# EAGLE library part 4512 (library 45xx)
8-channel DATA SELECTOR
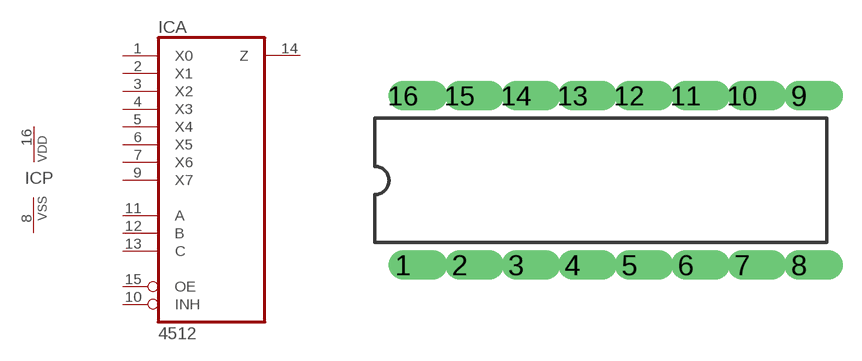
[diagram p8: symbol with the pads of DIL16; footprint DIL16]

Designator prefix IC; gates A=4512 P=PWRN

## 4512N  [DIL16]
1  A:X0  in
2  A:X1  in
3  A:X2  in
4  A:X3  in
5  A:X4  in
6  A:X5  in
7  A:X6  in
8  P:VSS  pwr
9  A:X7  in
10  A:INH  in
11  A:A  in
12  A:B  in
13  A:C  in
14  A:Z  hiz
15  A:OE  in
16  P:VDD  pwr

## Footprint DIL16 (pad centres in mm)
Dual In Line
drill 0.813 offset: 1 -8.89,-3.81; 2 -6.35,-3.81; 3 -3.81,-3.81; 4 -1.27,-3.81; 5 1.27,-3.81; 6 3.81,-3.81; 7 6.35,-3.81; 8 8.89,-3.81; 9 8.89,3.81; 10 6.35,3.81; 11 3.81,3.81; 12 1.27,3.81; 13 -1.27,3.81; 14 -3.81,3.81; 15 -6.35,3.81; 16 -8.89,3.81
